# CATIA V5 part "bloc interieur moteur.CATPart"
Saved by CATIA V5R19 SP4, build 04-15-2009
Part number: bloc interieur moteur
Bounding box of the stored display mesh (mm): x 0 to 48.73, y -47.035 to 56.042, z -42.8 to 21.065
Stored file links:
  G:\EU_thinkMotion\CFAO_2010\MMS_groupe1\MMS_groupe1\A reprendre\OK\rdeneffle\bloc interieur moteur.CATPart
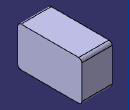
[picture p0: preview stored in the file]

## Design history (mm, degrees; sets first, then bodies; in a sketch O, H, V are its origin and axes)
Body1 (main body)
  Sketch1 on yz-plane, origin (0, 0, 0), H (0, 1, 0), V (0, 0, 1)
    line L1 (-47.0352, 21.0654) -> (56.0419, 21.0654)
    line L2 (56.0419, 21.0654) -> (56.0419, -42.7996)
    line L3 (56.0419, -42.7996) -> (-47.0352, -42.7996)
    line L4 (-47.0352, -42.7996) -> (-47.0352, 21.0654)
    horizontal: L1 H, L3 H
    vertical: L2 V, L4 V
  Pad1: profile Sketch1, direction (1, 0, 0), length 48.73
  Fillet1: radius 5, on edge [face of Pad1 from Sketch1.L1 | face of Pad1 from Sketch1.L2]; edge [face of Pad1 from Sketch1.L2 | face of Pad1 from Sketch1.L3]; edge [face of Pad1 from Sketch1.L4 | face of Pad1 from Sketch1.L1]; edge [face of Pad1 from Sketch1.L3 | face of Pad1 from Sketch1.L4]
